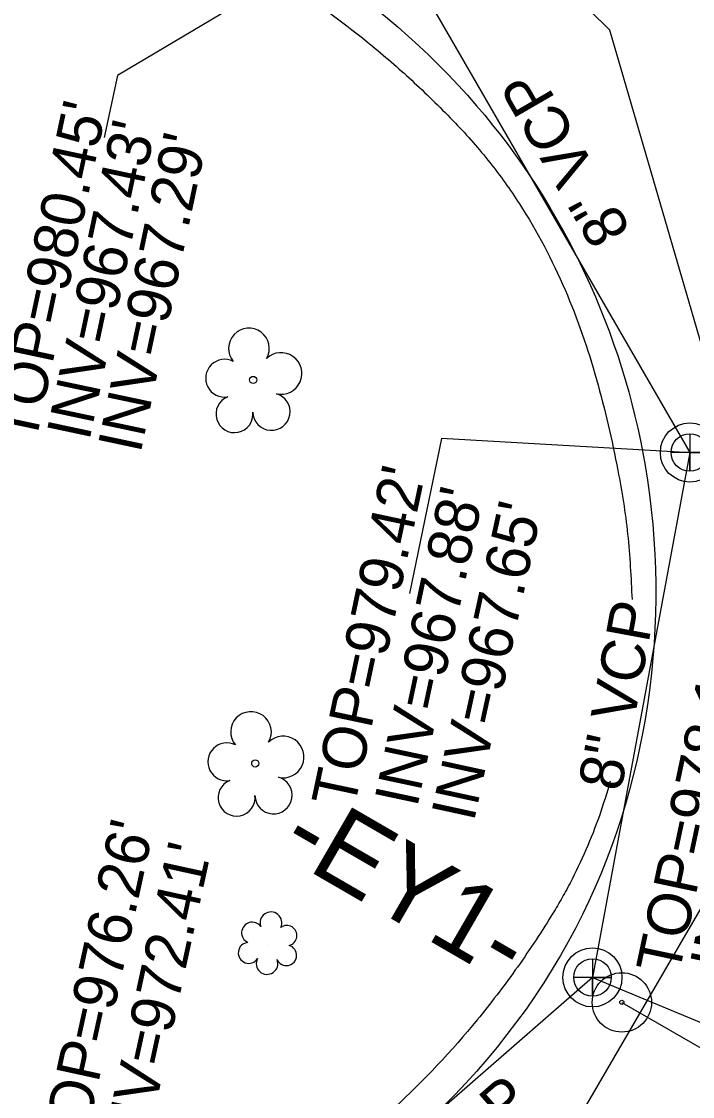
# Model space of a CAD drawing. Extents: x 1614611 to 1617571, y 898867 to 905462.
# Drawn here: x 1616326.4 to 1616387.7, y 901714.4 to 901812.5 of the extents above; entities that cross this region are included whole.
import ezdxf

# ---------------------------------------------------------------- set-up
doc = ezdxf.new("R2010")
doc.units = 0
for name, color, linetype in [('Exist Boundary Watershed Residential C 05', 7, 'Continuous'), ('Exist Horizontal Alignment Tick Label', 7, 'Continuous'), ('Exist Structure Minor Catch Basin Top Elevation', 7, 'Continuous'), ('Exist Structure Minor Pipes RCP 18 Inch Invert', 7, 'Continuous'), ('Exist Survey Centerline Point CELL', 7, 'Continuous'), ('Exist Utilities Sanitary Sewer Manhole Leader', 7, 'Continuous'), ('Exist Utilities Sanitary Sewer Manhole Text', 7, 'Continuous'), ('Exist Utilities Sanitary Sewer UG Line', 7, 'Continuous'), ('Exist Utilities Sanitary Sewer UG Line Invert Elevation', 7, 'Continuous'), ('Exist Utilities Sanitary Sewer UG Line Text', 7, 'Continuous'), ('Exist Utilities Water UG Line SUE LOS B', 7, 'Continuous'), ('Exist Vegetation Shrub CELL', 7, 'Continuous'), ('Exist Vegetation Tree CELL', 7, 'Continuous'), ('Old_Level_21', 7, 'Continuous'), ('Prop Drainage Structure Catch Basin Adjust Label', 7, 'Continuous'), ('Raster_Level_2', 7, 'Continuous'), ('Scratch_Level_9', 7, 'Continuous')]:
    doc.layers.add(name, color=color, linetype=linetype)

# ---------------------------------------------------------------- blocks, each defined once
blk = doc.blocks.new('EXIST UTILITIES SANITARY SEWER MANHOLE')
at = {"layer": 'Old_Level_21'}
blk.add_lwpolyline([(0, 0.03425), (0, -0.03425), (0, 0), (0.03425, 0), (-0.03425, 0)], dxfattribs=at)
for radius in [0.05389, 0.03425]:
    blk.add_circle((0, 0), radius, dxfattribs=at)
blk = doc.blocks.new('EXIST SURVEY CENTERLINE POINT')
at = {"layer": 'Exist Survey Centerline Point CELL'}
for radius in [0.0542, 0.00375]:
    blk.add_circle((0, 0), radius, dxfattribs=at)

msp = doc.modelspace()

# ---------------------------------------------------------------- linework, layer by layer
at = {"layer": 'Exist Boundary Watershed Residential C 05'}
for points in [[(1616332.674, 901824.098), (1616333.591, 901823.8), (1616338.068, 901822.204), (1616342.388, 901820.369), (1616350.624, 901815.903), (1616358.445, 901810.244), (1616362.246, 901806.918), (1616364.127, 901805.122), (1616365.998, 901803.235), (1616369.155, 901799.626), (1616371.845, 901795.871), (1616376.016, 901788.013), (1616378.889, 901779.839), (1616379.957, 901775.688), (1616380.842, 901771.525), (1616381.732, 901765.718), (1616382.136, 901759.747)], [(1616380.148, 901743.17), (1616379.15, 901740.021), (1616377.928, 901736.915), (1616376.469, 901733.865), (1616375.647, 901732.365), (1616374.763, 901730.882), (1616371.474, 901725.942), (1616367.998, 901721.394), (1616360.415, 901713.364), (1616351.871, 901706.561), (1616347.194, 901703.548), (1616342.224, 901700.756), (1616335.687, 901697.69), (1616328.899, 901695.991), (1616319.139, 901695.018)]]:
    msp.add_spline(points, degree=3, dxfattribs=at)
at = {"layer": 'Exist Utilities Sanitary Sewer Manhole Leader'}
for points in [[(1616359.233, 901821.871), (1616335.132, 901807.566), (1616333.925, 901801.914)], [(1616387.508, 901773.127), (1616364.725, 901774.443), (1616361.804, 901760.306)]]:
    msp.add_lwpolyline(points, dxfattribs=at)
at = {"layer": 'Exist Utilities Sanitary Sewer UG Line'}
for p, q in [((1616359.233, 901821.871), (1616387.413, 901773.168)), ((1616387.413, 901773.168), (1616378.522, 901725.261)), ((1616378.522, 901725.261), (1616329.348, 901682.401)), ((1616378.522, 901725.261), (1616482.734, 901681.778))]:
    msp.add_line(p, q, dxfattribs=at)
at = {"layer": 'Exist Utilities Water UG Line SUE LOS B'}
msp.add_lwpolyline([(1616329.451, 901690.357), (1616342.17, 901690.804), (1616365.695, 901696.571), (1616377.461, 901712.71), (1616391.131, 901736.186), (1616397.136, 901746.757), (1616391.334, 901773.206), (1616380.106, 901811.702), (1616365.353, 901826.253), (1616379.532, 901838.144), (1616381.442, 901842.738)], dxfattribs=at)
at = {"layer": 'Exist Vegetation Shrub CELL'}
msp.add_line((1616348.926, 901728.209), (1616348.926, 901728.209), dxfattribs=at)
for centre, radius, start, end in [((1616349.155, 901730.249), 0.99, 334.83907, 200.47174), ((1616347.443, 901729.335), 0.968, 35.89076, 245.42165), ((1616350.598, 901729.078), 0.929, 284.45672, 126.08612), ((1616347.126, 901727.504), 0.955, 95.10992, 327.95341), ((1616350.563, 901727.28), 0.937, 204.99133, 73.46012), ((1616348.798, 901726.525), 0.984, 151.27966, 21.38702)]:
    msp.add_arc(centre, radius, start, end, dxfattribs=at)
at = {"layer": 'Exist Vegetation Tree CELL'}
for p, q in [((1616347.529, 901779.789), (1616347.529, 901779.789)), ((1616347.721, 901744.789), (1616347.721, 901744.789))]:
    msp.add_line(p, q, dxfattribs=at)
for centre in [(1616347.529, 901779.789), (1616347.721, 901744.789)]:
    msp.add_circle(centre, 0.326, dxfattribs=at)
for centre, radius, start, end in [((1616347.144, 901782.663), 1.856, 330.16508, 219.71335), ((1616350.077, 901780.378), 1.899, 257.1011, 134.19993), ((1616344.923, 901779.943), 1.727, 62.66361, 279.3457), ((1616345.824, 901776.669), 1.689, 111.56708, 6.23104), ((1616349.201, 901776.89), 1.698, 181.28216, 74.55999), ((1616347.336, 901747.662), 1.856, 330.16508, 219.71335), ((1616345.115, 901744.943), 1.727, 62.66361, 279.3457), ((1616350.27, 901745.377), 1.899, 257.1011, 134.19993), ((1616346.017, 901741.668), 1.689, 111.56708, 6.23104), ((1616349.394, 901741.889), 1.698, 181.28216, 74.55999)]:
    msp.add_arc(centre, radius, start, end, dxfattribs=at)
at = {"layer": 'Raster_Level_2'}
msp.add_line((1616381.205, 901722.985), (1616409.402, 901706.662), dxfattribs=at)
at = {"layer": 'Scratch_Level_9'}
msp.add_spline([(1616333.277, 901826.538), (1616334.316, 901826.257), (1616367.937, 901804.817), (1616383.329, 901771.991), (1616376.998, 901729.791), (1616343.54, 901698.472), (1616329.293, 901693.555), (1616319.232, 901692.521), (1616318.569, 901692.524)], degree=3, dxfattribs=at)

# ---------------------------------------------------------------- block references
at = {"layer": 'Exist Horizontal Alignment Tick Label', "xscale": 50, "yscale": 50, "rotation": 1.7967031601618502e-12}
msp.add_blockref('EXIST SURVEY CENTERLINE POINT', (1616381.205, 901722.985), dxfattribs=at)
at = {"layer": 'Old_Level_21', "xscale": 50, "yscale": 50}
for p in [(1616387.413, 901773.168), (1616378.522, 901725.261)]:
    msp.add_blockref('EXIST UTILITIES SANITARY SEWER MANHOLE', p, dxfattribs=at)

# ---------------------------------------------------------------- texts
at = {"layer": 'Exist Structure Minor Catch Basin Top Elevation'}
msp.add_text("TOP=976.26'", height=4, rotation=77.71667, dxfattribs=at).set_placement((1616331.805, 901708.299))
at = {"layer": 'Exist Structure Minor Pipes RCP 18 Inch Invert'}
msp.add_text("INV=972.41'", height=4, rotation=77.71667, dxfattribs=at).set_placement((1616337.497, 901708.27))
at = {"layer": 'Exist Utilities Sanitary Sewer Manhole Text'}
for s, p in [("TOP=980.45'", (1616327.645, 901773.883)), ("TOP=979.42'", (1616356.754, 901740.587)), ("TOP=978.13'", (1616386.399, 901725.38))]:
    msp.add_text(s, height=4, rotation=78.01667, dxfattribs=at).set_placement(p)
at = {"layer": 'Exist Utilities Sanitary Sewer UG Line Invert Elevation'}
for s, height, rotation, p in [("INV=967.43'", 4, 78.01667, (1616332.559, 901774.141)), ("INV=967.29'", 4, 78.01667, (1616337.233, 901772.991)), ("INV=967.88'", 4.0017, 78.01667, (1616362.505, 901740.675)), ("INV=967.65'", 4.0017, 77.71667, (1616367.683, 901739.373)), ("INV=968.21'", 4, 78.01667, (1616391.299, 901725.684))]:
    msp.add_text(s, height=height, rotation=rotation, dxfattribs=at).set_placement(p)
at = {"layer": 'Exist Utilities Sanitary Sewer UG Line Text'}
for rotation, p in [(120.05407, (1616382.094, 901793.468)), (79.48617, (1616381.121, 901742.137)), (41.07537, (1616360.071, 901702.209))]:
    msp.add_text('8" VCP', height=4, rotation=rotation, dxfattribs=at).set_placement(p)
at = {"layer": 'Prop Drainage Structure Catch Basin Adjust Label'}
msp.add_text('-EY1-', height=7, rotation=329.93333, dxfattribs=at).set_placement((1616349.694, 901736.664))

doc.saveas('drawing.dxf')
